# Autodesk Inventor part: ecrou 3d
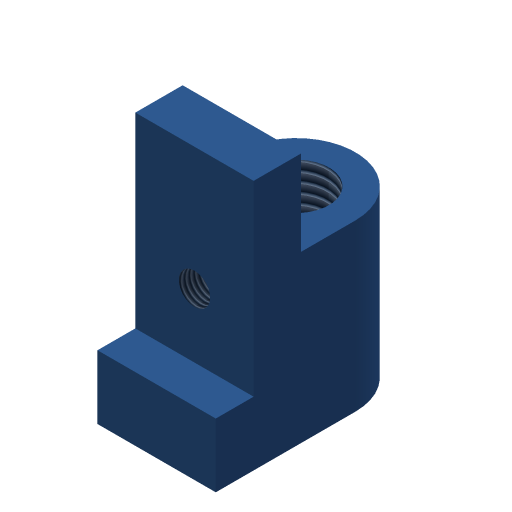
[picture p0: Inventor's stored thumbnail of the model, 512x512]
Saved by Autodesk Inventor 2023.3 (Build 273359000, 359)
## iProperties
Shininess: 21.0
Length Units: 11269
Angle Units: 11279
Time Units: 11290
Mass Units: 11283
Length Display Precision: 3
Angle Display Precision: 2
Created: 2001-10
Part Number: ecrou 3d
Material: Générique
Document SubType Name: Proxy Part
Designer: ajt
Density: 1 g/cm^3
Appearance: Bleu (ciel)
Density: 0.0
Volumn: 0.0
Area: 0.0
PropertySet Name: Model Information
Control State: 0
Master: False
Checked Out: False
Author: ajt
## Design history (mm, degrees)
feature "LinkedPart1"
feature "Filetage1" dims "d0" = 10, "d1" = 0
feature "Filetage2" dims "d2" = 35, "d3" = 0
node "Solide1"
node "Corps solides"
node "Corps surfaciques"
